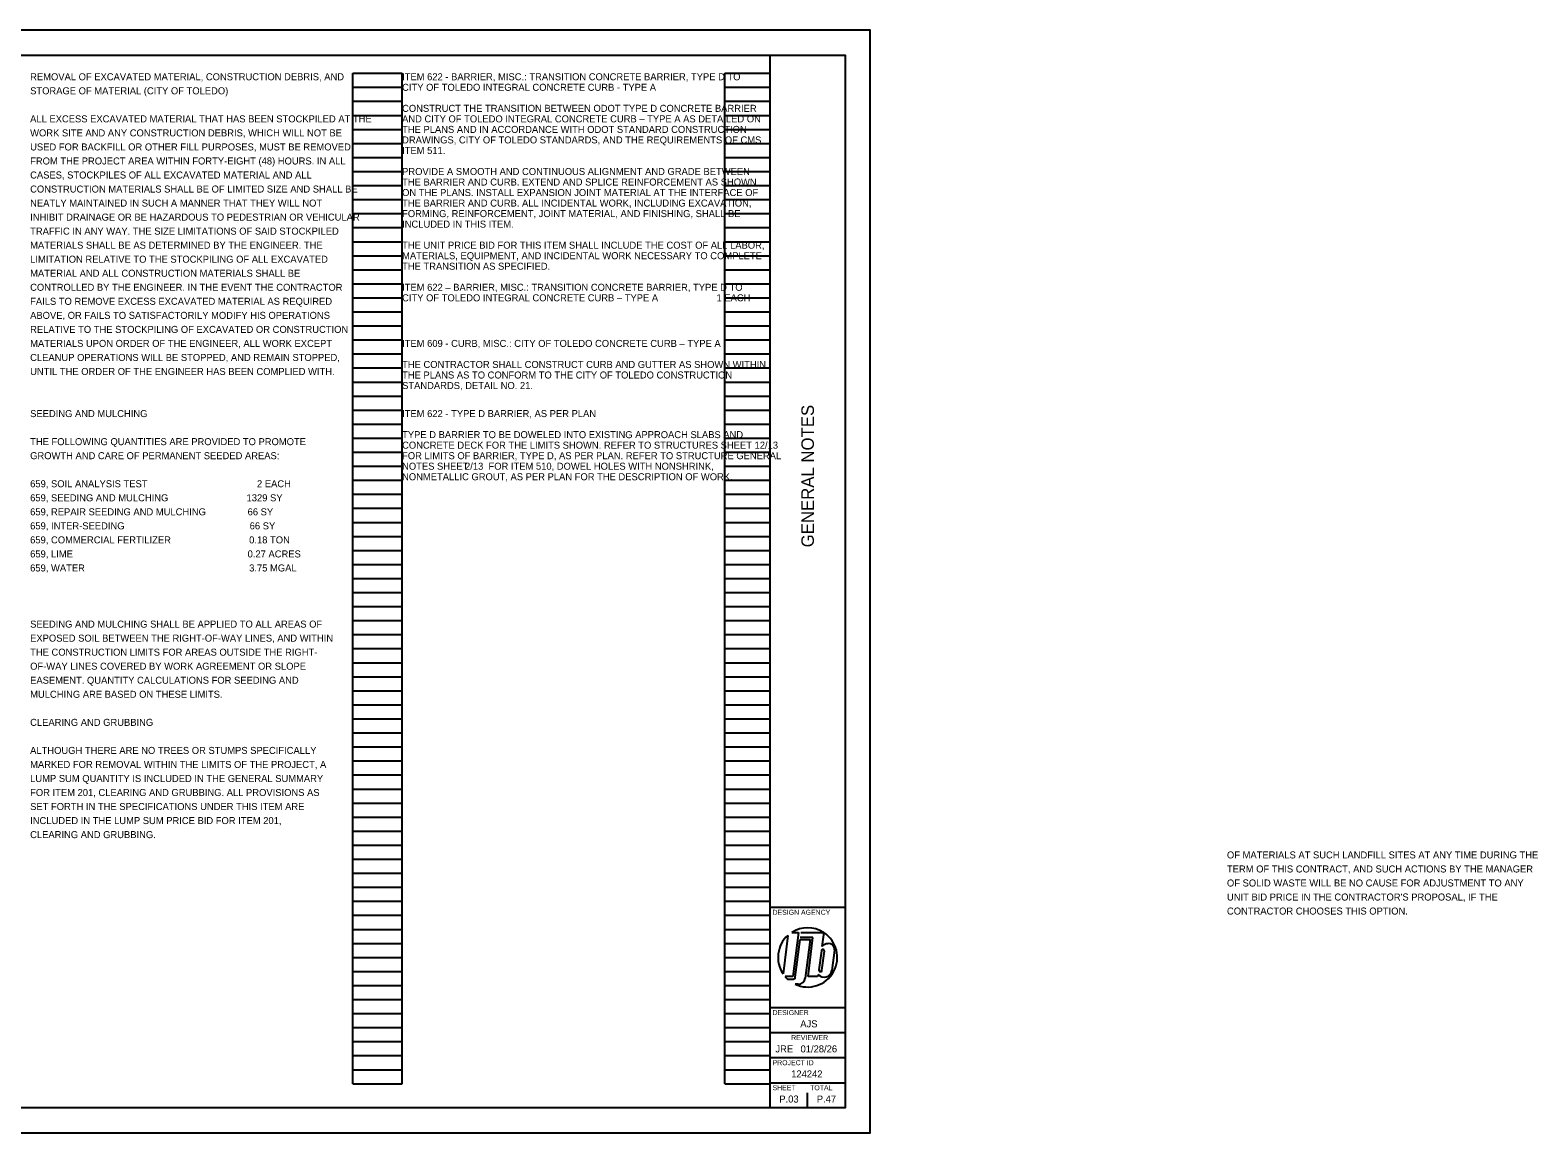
# Model space of a CAD drawing. Extents: x 0 to 47.3, y -11.1 to 22.
# Drawn here: x 17.24 to 47.32, y 0 to 22 of the extents above; entities that cross this region are included whole.
import ezdxf

# ---------------------------------------------------------------- set-up
doc = ezdxf.new("R2010")
doc.units = 0
for name, color, linetype in [('SH_Border', 7, 'Continuous'), ('SH_Cut_Line', 7, 'Continuous'), ('SH_Data', 7, 'Continuous'), ('SH_Text', 7, 'Continuous')]:
    doc.layers.add(name, color=color, linetype=linetype)

msp = doc.modelspace()

# ---------------------------------------------------------------- linework, layer by layer
at = {"layer": 'SH_Border'}
for p, q in [((32, 0.5), (32, 21.5)), ((32, 4.5), (33.5, 4.5)), ((32, 2.5), (33.5, 2.5)), ((32, 2), (33.5, 2)), ((32, 1.5), (33.5, 1.5)), ((32, 1), (33.5, 1))]:
    msp.add_line(p, q, dxfattribs=at)
msp.add_lwpolyline([(1.5, 21.5), (33.5, 21.5), (33.5, 0.5), (1.5, 0.5)], close=True, dxfattribs=at)
at = {"layer": 'SH_Cut_Line'}
msp.add_lwpolyline([(0, 0), (34, 0), (34, 22), (0, 22)], close=True, dxfattribs=at)
at = {"layer": 'SH_Data'}
for p, q in [((23.68, 0.98), (23.68, 21.14)), ((23.68, 21.14), (24.66, 21.14)), ((24.66, 0.98), (24.66, 21.14)), ((31.1, 0.98), (31.1, 21.14)), ((31.1, 21.14), (32, 21.14)), ((32, 0.98), (32, 21.14)), ((23.68, 20.86), (24.66, 20.86)), ((31.1, 20.86), (32, 20.86)), ((23.68, 20.58), (24.66, 20.58)), ((31.1, 20.58), (32, 20.58)), ((23.68, 20.3), (24.66, 20.3)), ((31.1, 20.3), (32, 20.3)), ((23.68, 20.02), (24.66, 20.02)), ((31.1, 20.02), (32, 20.02)), ((23.68, 19.74), (24.66, 19.74)), ((31.1, 19.74), (32, 19.74)), ((23.68, 19.46), (24.66, 19.46)), ((31.1, 19.46), (32, 19.46)), ((23.68, 19.18), (24.66, 19.18)), ((31.1, 19.18), (32, 19.18)), ((23.68, 18.9), (24.66, 18.9)), ((31.1, 18.9), (32, 18.9)), ((23.68, 18.62), (24.66, 18.62)), ((31.1, 18.62), (32, 18.62)), ((23.68, 18.34), (24.66, 18.34)), ((23.68, 18.06), (24.66, 18.06)), ((31.1, 18.34), (32, 18.34)), ((31.1, 18.06), (32, 18.06)), ((23.68, 17.78), (24.66, 17.78)), ((31.1, 17.78), (32, 17.78)), ((23.68, 17.5), (24.66, 17.5)), ((31.1, 17.5), (32, 17.5)), ((23.68, 17.22), (24.66, 17.22)), ((31.1, 17.22), (32, 17.22)), ((23.68, 16.94), (24.66, 16.94)), ((31.1, 16.94), (32, 16.94)), ((23.68, 16.66), (24.66, 16.66)), ((31.1, 16.66), (32, 16.66)), ((23.68, 16.38), (24.66, 16.38)), ((31.1, 16.38), (32, 16.38)), ((23.68, 16.1), (24.66, 16.1)), ((31.1, 16.1), (32, 16.1)), ((23.68, 15.82), (24.66, 15.82)), ((31.1, 15.82), (32, 15.82)), ((23.68, 15.54), (24.66, 15.54)), ((31.1, 15.54), (32, 15.54)), ((23.68, 15.26), (24.66, 15.26)), ((31.1, 15.26), (32, 15.26)), ((23.68, 14.98), (24.66, 14.98)), ((31.1, 14.98), (32, 14.98)), ((23.68, 14.7), (24.66, 14.7)), ((31.1, 14.7), (32, 14.7)), ((23.68, 14.42), (24.66, 14.42)), ((23.68, 14.14), (24.66, 14.14)), ((31.1, 14.42), (32, 14.42)), ((31.1, 14.14), (32, 14.14)), ((23.68, 13.86), (24.66, 13.86)), ((31.1, 13.86), (32, 13.86)), ((23.68, 13.58), (24.66, 13.58)), ((31.1, 13.58), (32, 13.58)), ((23.68, 13.3), (24.66, 13.3)), ((31.1, 13.3), (32, 13.3)), ((23.68, 13.02), (24.66, 13.02)), ((31.1, 13.02), (32, 13.02)), ((23.68, 12.74), (24.66, 12.74)), ((31.1, 12.74), (32, 12.74)), ((23.68, 12.46), (24.66, 12.46)), ((31.1, 12.46), (32, 12.46)), ((23.68, 12.18), (24.66, 12.18)), ((31.1, 12.18), (32, 12.18)), ((23.68, 11.9), (24.66, 11.9)), ((31.1, 11.9), (32, 11.9)), ((23.68, 11.62), (24.66, 11.62)), ((31.1, 11.62), (32, 11.62)), ((23.68, 11.34), (24.66, 11.34)), ((31.1, 11.34), (32, 11.34)), ((23.68, 11.06), (24.66, 11.06)), ((31.1, 11.06), (32, 11.06)), ((23.68, 10.78), (24.66, 10.78)), ((31.1, 10.78), (32, 10.78)), ((23.68, 10.5), (24.66, 10.5)), ((31.1, 10.5), (32, 10.5)), ((23.68, 10.22), (24.66, 10.22)), ((23.68, 9.94), (24.66, 9.94)), ((31.1, 10.22), (32, 10.22)), ((31.1, 9.94), (32, 9.94)), ((23.68, 9.66), (24.66, 9.66)), ((31.1, 9.66), (32, 9.66)), ((23.68, 9.38), (24.66, 9.38)), ((31.1, 9.38), (32, 9.38)), ((23.68, 9.1), (24.66, 9.1)), ((31.1, 9.1), (32, 9.1)), ((23.68, 8.82), (24.66, 8.82)), ((31.1, 8.82), (32, 8.82)), ((23.68, 8.54), (24.66, 8.54)), ((31.1, 8.54), (32, 8.54)), ((23.68, 8.26), (24.66, 8.26)), ((31.1, 8.26), (32, 8.26)), ((23.68, 7.98), (24.66, 7.98)), ((31.1, 7.98), (32, 7.98)), ((23.68, 7.7), (24.66, 7.7)), ((31.1, 7.7), (32, 7.7)), ((23.68, 7.42), (24.66, 7.42)), ((31.1, 7.42), (32, 7.42)), ((23.68, 7.14), (24.66, 7.14)), ((31.1, 7.14), (32, 7.14)), ((23.68, 6.86), (24.66, 6.86)), ((31.1, 6.86), (32, 6.86)), ((23.68, 6.58), (24.66, 6.58)), ((31.1, 6.58), (32, 6.58)), ((23.68, 6.3), (24.66, 6.3)), ((23.68, 6.02), (24.66, 6.02)), ((31.1, 6.3), (32, 6.3)), ((31.1, 6.02), (32, 6.02)), ((23.68, 5.74), (24.66, 5.74)), ((31.1, 5.74), (32, 5.74)), ((23.68, 5.46), (24.66, 5.46)), ((31.1, 5.46), (32, 5.46)), ((23.68, 5.18), (24.66, 5.18)), ((31.1, 5.18), (32, 5.18)), ((23.68, 4.9), (24.66, 4.9)), ((31.1, 4.9), (32, 4.9)), ((23.68, 4.62), (24.66, 4.62)), ((31.1, 4.62), (32, 4.62)), ((23.68, 4.34), (24.66, 4.34)), ((31.1, 4.34), (32, 4.34)), ((23.68, 4.06), (24.66, 4.06)), ((31.1, 4.06), (32, 4.06)), ((32.356, 3.94), (32.259, 3.171)), ((32.432, 3.998), (32.567, 3.998)), ((32.567, 3.998), (32.456, 3.118)), ((32.617, 4), (33.065, 4)), ((33.07, 3.996), (33.035, 3.72)), ((23.68, 3.78), (24.66, 3.78)), ((31.1, 3.78), (32, 3.78)), ((32.504, 3.104), (32.599, 3.855)), ((32.599, 3.855), (32.801, 3.855)), ((32.856, 3.896), (32.604, 3.896)), ((32.801, 3.855), (32.704, 3.089)), ((32.758, 3.118), (32.856, 3.896)), ((33.024, 3.631), (32.976, 3.25)), ((33.036, 3.243), (33.084, 3.624)), ((33.283, 3.648), (33.231, 3.237)), ((23.68, 3.5), (24.66, 3.5)), ((31.1, 3.5), (32, 3.5)), ((32.75, 3.5), (32.75, 3.5)), ((23.68, 3.22), (24.66, 3.22)), ((31.1, 3.22), (32, 3.22)), ((32.456, 3.118), (32.299, 3.118)), ((32.347, 3.068), (32.462, 3.068)), ((32.947, 3.118), (32.758, 3.118)), ((32.964, 3.161), (32.947, 3.118)), ((23.68, 2.94), (24.66, 2.94)), ((31.1, 2.94), (32, 2.94)), ((32.564, 2.966), (32.498, 2.966)), ((23.68, 2.66), (24.66, 2.66)), ((31.1, 2.66), (32, 2.66)), ((23.68, 2.38), (24.66, 2.38)), ((31.1, 2.38), (32, 2.38)), ((23.68, 2.1), (24.66, 2.1)), ((23.68, 1.82), (24.66, 1.82)), ((31.1, 2.1), (32, 2.1)), ((31.1, 1.82), (32, 1.82)), ((23.68, 1.54), (24.66, 1.54)), ((31.1, 1.54), (32, 1.54)), ((23.68, 1.26), (24.66, 1.26)), ((31.1, 1.26), (32, 1.26)), ((23.68, 0.98), (24.66, 0.98)), ((31.1, 0.98), (32, 0.98)), ((32.375, 0.675), (32.375, 0.675)), ((32.75, 0.5), (32.75, 0.8))]:
    msp.add_line(p, q, dxfattribs=at)
for centre, radius, start, end in [((32.75, 3.5), 0.591, 131.8253, 213.7822), ((32.75, 3.5), 0.591, 57.726, 122.5688), ((32.75, 3.5), 0.591, 244.7646, 57.1575), ((33.054, 3.628), 0.0301, 352.3298, 173.2777), ((33.17, 3.586), 0.19, 105.9444, 135.0487), ((33.164, 3.6), 0.175, 66.6782, 105.4185), ((33.177, 3.669), 0.108, 349.2072, 58.7163), ((32.75, 3.5), 0.591, 220.2786, 227.0158), ((32.462, 3.109), 0.0417, 270, 352.8038), ((32.564, 3.106), 0.141, 270, 352.8038), ((33.081, 3.255), 0.151, 218.6264, 353.0883), ((33.006, 3.246), 0.0301, 172.3335, 353.274)]:
    msp.add_arc(centre, radius, start, end, dxfattribs=at)

# ---------------------------------------------------------------- texts
msp.add_text('GENERAL NOTES', height=0.25, rotation=90, dxfattribs=at).set_placement((32.875, 11.682))
for s, height, p in [('DESIGN AGENCY', 0.1, (32.05, 4.35)), ('DESIGNER', 0.1, (32.05, 2.35)), ('AJS', 0.14, (32.603, 2.105)), ('REVIEWER', 0.1, (32.422, 1.85)), ('JRE', 0.14, (32.107, 1.605)), ('01/28/26', 0.14, (32.609, 1.605)), ('PROJECT ID', 0.1, (32.05, 1.35)), ('124242', 0.14, (32.421, 1.105)), ('SHEET', 0.1, (32.05, 0.85)), ('TOTAL', 0.1, (32.8, 0.85)), ('P.03', 0.14, (32.185, 0.605)), ('P.47', 0.14, (32.933, 0.605))]:
    msp.add_text(s, height=height, dxfattribs=at).set_placement(p)
at = {"layer": 'SH_Text'}
for s, p in [('REMOVAL OF EXCAVATED MATERIAL, CONSTRUCTION DEBRIS, AND', (17.24, 21)), ('ITEM 622 - BARRIER, MISC.: TRANSITION CONCRETE BARRIER, TYPE D TO ', (24.66, 21)), ('STORAGE OF MATERIAL (CITY OF TOLEDO)', (17.24, 20.72)), ('CITY OF TOLEDO INTEGRAL CONCRETE CURB - TYPE A', (24.66, 20.79)), ('CONSTRUCT THE TRANSITION BETWEEN ODOT TYPE D CONCRETE BARRIER ', (24.66, 20.37)), ('ALL EXCESS EXCAVATED MATERIAL THAT HAS BEEN STOCKPILED AT THE', (17.24, 20.16)), ('AND CITY OF TOLEDO INTEGRAL CONCRETE CURB – TYPE A AS DETAILED ON ', (24.66, 20.16)), ('WORK SITE AND ANY CONSTRUCTION DEBRIS, WHICH WILL NOT BE', (17.24, 19.88)), ('THE PLANS AND IN ACCORDANCE WITH ODOT STANDARD CONSTRUCTION ', (24.66, 19.95)), ('DRAWINGS, CITY OF TOLEDO STANDARDS, AND THE REQUIREMENTS OF CMS ', (24.66, 19.74)), ('USED FOR BACKFILL OR OTHER FILL PURPOSES, MUST BE REMOVED', (17.24, 19.6)), ('ITEM 511.', (24.66, 19.53)), ('FROM THE PROJECT AREA WITHIN FORTY-EIGHT (48) HOURS. IN ALL', (17.24, 19.32)), ('PROVIDE A SMOOTH AND CONTINUOUS ALIGNMENT AND GRADE BETWEEN ', (24.66, 19.11)), ('CASES, STOCKPILES OF ALL EXCAVATED MATERIAL AND ALL', (17.24, 19.04)), ('THE BARRIER AND CURB. EXTEND AND SPLICE REINFORCEMENT AS SHOWN ', (24.66, 18.9)), ('CONSTRUCTION MATERIALS SHALL BE OF LIMITED SIZE AND SHALL BE', (17.24, 18.76)), ('ON THE PLANS. INSTALL EXPANSION JOINT MATERIAL AT THE INTERFACE OF ', (24.66, 18.69)), ('NEATLY MAINTAINED IN SUCH A MANNER THAT THEY WILL NOT', (17.24, 18.48)), ('THE BARRIER AND CURB. ALL INCIDENTAL WORK, INCLUDING EXCAVATION, ', (24.66, 18.48)), ('FORMING, REINFORCEMENT, JOINT MATERIAL, AND FINISHING, SHALL BE ', (24.66, 18.27)), ('TRAFFIC IN ANY WAY. THE SIZE LIMITATIONS OF SAID STOCKPILED', (17.24, 17.92)), ('INHIBIT DRAINAGE OR BE HAZARDOUS TO PEDESTRIAN OR VEHICULAR', (17.24, 18.2)), ('INCLUDED IN THIS ITEM.', (24.66, 18.06)), ('MATERIALS SHALL BE AS DETERMINED BY THE ENGINEER. THE', (17.24, 17.64)), ('THE UNIT PRICE BID FOR THIS ITEM SHALL INCLUDE THE COST OF ALL LABOR, ', (24.66, 17.64)), ('LIMITATION RELATIVE TO THE STOCKPILING OF ALL EXCAVATED', (17.24, 17.36)), ('MATERIALS, EQUIPMENT, AND INCIDENTAL WORK NECESSARY TO COMPLETE ', (24.66, 17.43)), ('MATERIAL AND ALL CONSTRUCTION MATERIALS SHALL BE', (17.24, 17.08)), ('THE TRANSITION AS SPECIFIED.', (24.66, 17.22)), ('CONTROLLED BY THE ENGINEER. IN THE EVENT THE CONTRACTOR', (17.24, 16.8)), ('ITEM 622 – BARRIER, MISC.: TRANSITION CONCRETE BARRIER, TYPE D TO ', (24.66, 16.8)), ('FAILS TO REMOVE EXCESS EXCAVATED MATERIAL AS REQUIRED', (17.24, 16.52)), ('CITY OF TOLEDO INTEGRAL CONCRETE CURB – TYPE A     ', (24.66, 16.59)), ('                        1 EACH', (29.684, 16.59)), ('ABOVE, OR FAILS TO SATISFACTORILY MODIFY HIS OPERATIONS', (17.24, 16.24)), ('RELATIVE TO THE STOCKPILING OF EXCAVATED OR CONSTRUCTION', (17.24, 15.96)), ('MATERIALS UPON ORDER OF THE ENGINEER, ALL WORK EXCEPT', (17.24, 15.68)), ('ITEM 609 - CURB, MISC.: CITY OF TOLEDO CONCRETE CURB – TYPE A', (24.66, 15.68)), ('CLEANUP OPERATIONS WILL BE STOPPED, AND REMAIN STOPPED,', (17.24, 15.4)), ('THE CONTRACTOR SHALL CONSTRUCT CURB AND GUTTER AS SHOWN WITHIN ', (24.66, 15.26)), ('UNTIL THE ORDER OF THE ENGINEER HAS BEEN COMPLIED WITH.', (17.24, 15.12)), ('THE PLANS AS TO CONFORM TO THE CITY OF TOLEDO CONSTRUCTION ', (24.66, 15.05)), ('STANDARDS, DETAIL NO. 21. ', (24.66, 14.84)), ('SEEDING AND MULCHING', (17.24, 14.28)), ('ITEM 622 - TYPE D BARRIER, AS PER PLAN', (24.66, 14.28)), ('THE FOLLOWING QUANTITIES ARE PROVIDED TO PROMOTE', (17.24, 13.72)), ('TYPE D BARRIER TO BE DOWELED INTO EXISTING APPROACH SLABS AND ', (24.66, 13.86)), ('GROWTH AND CARE OF PERMANENT SEEDED AREAS:', (17.24, 13.44)), ('CONCRETE DECK FOR THE LIMITS SHOWN. REFER TO STRUCTURES SHEET 12/13 ', (24.66, 13.65)), ('FOR LIMITS OF BARRIER, TYPE D, AS PER PLAN. REFER TO STRUCTURE GENERAL ', (24.66, 13.44)), ('NOTES SHEET', (24.66, 13.23)), (' 2/13 ', (25.863, 13.23)), ('FOR ITEM 510, DOWEL HOLES WITH NONSHRINK, ', (26.384, 13.23)), ('659, SOIL ANALYSIS TEST                                          2 EACH', (17.24, 12.88)), ('NONMETALLIC GROUT, AS PER PLAN FOR THE DESCRIPTION OF WORK.', (24.66, 13.02)), ('659, SEEDING AND MULCHING                              1329 SY', (17.24, 12.6)), ('659, REPAIR SEEDING AND MULCHING                66 SY', (17.24, 12.32)), ('659, INTER-SEEDING                                                66 SY', (17.24, 12.04)), ('659, COMMERCIAL FERTILIZER                              0.18 TON', (17.24, 11.76)), ('659, LIME                                                                   0.27 ACRES', (17.24, 11.48)), ('659, WATER                                                               3.75 MGAL', (17.24, 11.2)), ('SEEDING AND MULCHING SHALL BE APPLIED TO ALL AREAS OF', (17.24, 10.08)), ('EXPOSED SOIL BETWEEN THE RIGHT-OF-WAY LINES, AND WITHIN', (17.24, 9.8)), ('THE CONSTRUCTION LIMITS FOR AREAS OUTSIDE THE RIGHT-', (17.24, 9.52)), ('OF-WAY LINES COVERED BY WORK AGREEMENT OR SLOPE', (17.24, 9.24)), ('EASEMENT. QUANTITY CALCULATIONS FOR SEEDING AND', (17.24, 8.96)), ('MULCHING ARE BASED ON THESE LIMITS.', (17.24, 8.68)), ('CLEARING AND GRUBBING', (17.24, 8.12)), ('ALTHOUGH THERE ARE NO TREES OR STUMPS SPECIFICALLY', (17.24, 7.56)), ('MARKED FOR REMOVAL WITHIN THE LIMITS OF THE PROJECT, A', (17.24, 7.28)), ('LUMP SUM QUANTITY IS INCLUDED IN THE GENERAL SUMMARY', (17.24, 7)), ('FOR ITEM 201, CLEARING AND GRUBBING. ALL PROVISIONS AS', (17.24, 6.72)), ('SET FORTH IN THE SPECIFICATIONS UNDER THIS ITEM ARE', (17.24, 6.44)), ('CLEARING AND GRUBBING.', (17.24, 5.88)), ('INCLUDED IN THE LUMP SUM PRICE BID FOR ITEM 201,', (17.24, 6.16)), ('         OF MATERIALS AT SUCH LANDFILL SITES AT ANY TIME DURING THE', (40.647, 5.475)), ('         TERM OF THIS CONTRACT, AND SUCH ACTIONS BY THE MANAGER', (40.647, 5.195)), ('         OF SOLID WASTE WILL BE NO CAUSE FOR ADJUSTMENT TO ANY', (40.647, 4.915)), ("         UNIT BID PRICE IN THE CONTRACTOR'S PROPOSAL, IF THE", (40.647, 4.635)), ('         CONTRACTOR CHOOSES THIS OPTION.', (40.647, 4.355))]:
    msp.add_text(s, height=0.14, dxfattribs=at).set_placement(p)

doc.saveas('drawing.dxf')
